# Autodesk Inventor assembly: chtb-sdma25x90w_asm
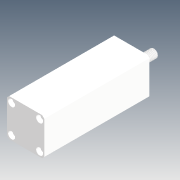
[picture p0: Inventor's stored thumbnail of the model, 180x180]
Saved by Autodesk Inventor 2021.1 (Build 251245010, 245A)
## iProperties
Company: Microsoft
Created: 2018-05
Part Number: chtb-sdma25x90w_asm
Description: STEP AP214
Document SubType Name: Assembly
Designer: user
Title: chtb-sdma25x90w_asm.STEP
Author: Windows
Revision Number: ÈÎºÎ
Sending System: SolidWorks 2015
Preprocessor: SwSTEP 2.0
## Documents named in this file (4)
- D:\Vault_2016\Projekty\Clamptek\Hydraulic\CHTB\CHTB-25\Inventor\chtb-sdma25x90w\chtb-sdma25x90w_asm.iam
- D:\Vault_2016\Projekty\Clamptek\Hydraulic\CHTB\CHTB-25\Inventor\chtb-sdma25x90w\CHTB-25QG.ipt
- D:\Vault_2016\Projekty\Clamptek\Hydraulic\CHTB\CHTB-25\Inventor\chtb-sdma25x90w\CHTB-SDMA25X90NBT.ipt
- D:\Vault_2016\Projekty\Clamptek\Hydraulic\CHTB\CHTB-25\Inventor\chtb-sdma25x90w\CHTB-SDMA25X90WHSG.ipt
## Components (3 placed, 3 different names)
1. CHTB-25QG_1
2. CHTB-SDMA25X90NBT_2
3. CHTB-SDMA25X90WHSG_3
